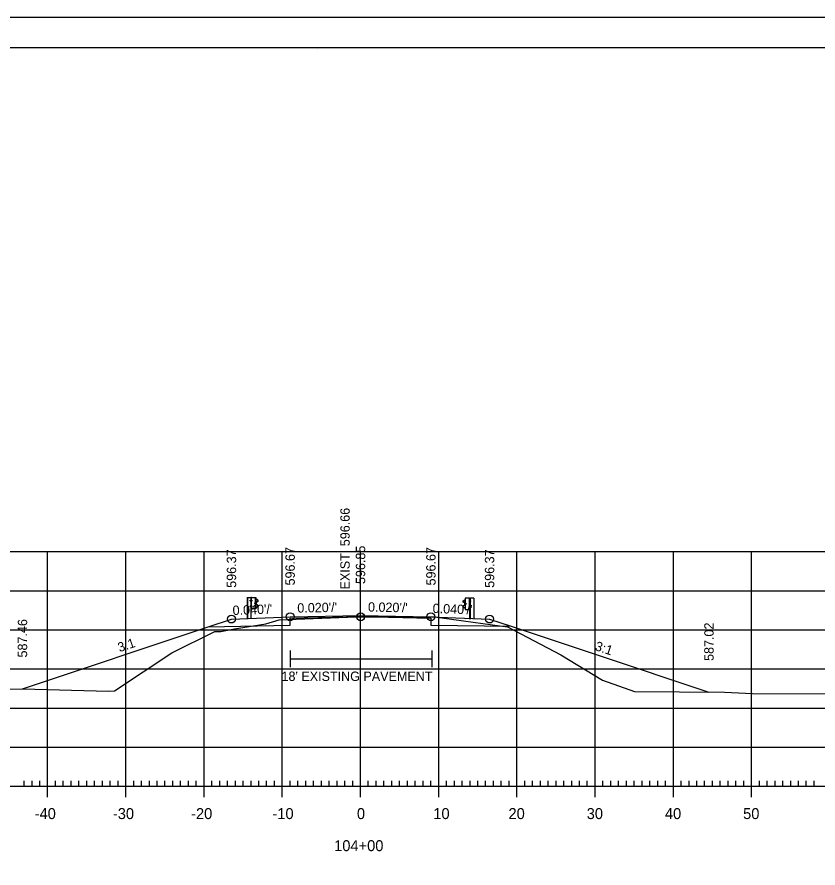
# Model space of a CAD drawing. Extents: x 961436 to 1372525, y 380079 to 2027791.
# Drawn here: x 1370589.9 to 1370692.3, y 380213.6 to 380322.4 of the extents above; entities that cross this region are included whole.
import ezdxf

# ---------------------------------------------------------------- set-up
doc = ezdxf.new("R2010")
doc.units = 0
for name, color, linetype in [('R_Alt Surface', 7, 'Continuous'), ('R_Axis', 7, 'Continuous'), ('R_Axis Annot', 7, 'Continuous'), ('R_Drive', 7, 'Continuous'), ('R_Exist Surface', 7, 'Continuous'), ('R_Fin Surface', 7, 'Continuous'), ('R_Fin Surface Annot', 7, 'Continuous'), ('R_Grid', 7, 'Continuous'), ('R_No Plot', 7, 'Continuous'), ('R_Proposed Road', 7, 'Continuous'), ('R_Xsect Elev', 7, 'Continuous')]:
    doc.layers.add(name, color=color, linetype=linetype)

msp = doc.modelspace()

# ---------------------------------------------------------------- linework, layer by layer
at = {"layer": 'R_Alt Surface'}
msp.add_lwpolyline([(1370614.33, 380244.44), (1370624.81, 380244.65), (1370624.8, 380244.65), (1370624.81, 380245.56), (1370633.81, 380245.74), (1370642.81, 380245.56), (1370642.82, 380244.65), (1370642.81, 380244.65), (1370653.07, 380244.51)], dxfattribs=at)
at = {"layer": 'R_Axis'}
for p, q in [((1370593.81, 380222.66), (1370593.81, 380225.46)), ((1370603.81, 380222.66), (1370603.81, 380225.46)), ((1370613.81, 380222.66), (1370613.81, 380225.46)), ((1370623.81, 380222.66), (1370623.81, 380225.46)), ((1370633.81, 380222.66), (1370633.81, 380225.46)), ((1370643.81, 380222.66), (1370643.81, 380225.46)), ((1370653.81, 380222.66), (1370653.81, 380225.46)), ((1370663.81, 380222.66), (1370663.81, 380225.46)), ((1370673.81, 380222.66), (1370673.81, 380225.46)), ((1370683.81, 380222.66), (1370683.81, 380225.46)), ((1370493.81, 380224.06), (1370773.81, 380224.06)), ((1370590.81, 380224.06), (1370590.81, 380224.76)), ((1370591.81, 380224.06), (1370591.81, 380224.76)), ((1370592.81, 380224.06), (1370592.81, 380224.76)), ((1370594.81, 380224.06), (1370594.81, 380224.76)), ((1370595.81, 380224.06), (1370595.81, 380224.76)), ((1370596.81, 380224.06), (1370596.81, 380224.76)), ((1370597.81, 380224.06), (1370597.81, 380224.76)), ((1370598.81, 380224.06), (1370598.81, 380224.76)), ((1370599.81, 380224.06), (1370599.81, 380224.76)), ((1370600.81, 380224.06), (1370600.81, 380224.76)), ((1370601.81, 380224.06), (1370601.81, 380224.76)), ((1370602.81, 380224.06), (1370602.81, 380224.76)), ((1370604.81, 380224.06), (1370604.81, 380224.76)), ((1370605.81, 380224.06), (1370605.81, 380224.76)), ((1370606.81, 380224.06), (1370606.81, 380224.76)), ((1370607.81, 380224.06), (1370607.81, 380224.76)), ((1370608.81, 380224.06), (1370608.81, 380224.76)), ((1370609.81, 380224.06), (1370609.81, 380224.76)), ((1370610.81, 380224.06), (1370610.81, 380224.76)), ((1370611.81, 380224.06), (1370611.81, 380224.76)), ((1370612.81, 380224.06), (1370612.81, 380224.76)), ((1370614.81, 380224.06), (1370614.81, 380224.76)), ((1370615.81, 380224.06), (1370615.81, 380224.76)), ((1370616.81, 380224.06), (1370616.81, 380224.76)), ((1370617.81, 380224.06), (1370617.81, 380224.76)), ((1370618.81, 380224.06), (1370618.81, 380224.76)), ((1370619.81, 380224.06), (1370619.81, 380224.76)), ((1370620.81, 380224.06), (1370620.81, 380224.76)), ((1370621.81, 380224.06), (1370621.81, 380224.76)), ((1370622.81, 380224.06), (1370622.81, 380224.76)), ((1370624.81, 380224.06), (1370624.81, 380224.76)), ((1370625.81, 380224.06), (1370625.81, 380224.76)), ((1370626.81, 380224.06), (1370626.81, 380224.76)), ((1370627.81, 380224.06), (1370627.81, 380224.76)), ((1370628.81, 380224.06), (1370628.81, 380224.76)), ((1370629.81, 380224.06), (1370629.81, 380224.76)), ((1370630.81, 380224.06), (1370630.81, 380224.76)), ((1370631.81, 380224.06), (1370631.81, 380224.76)), ((1370632.81, 380224.06), (1370632.81, 380224.76)), ((1370634.81, 380224.06), (1370634.81, 380224.76)), ((1370635.81, 380224.06), (1370635.81, 380224.76)), ((1370636.81, 380224.06), (1370636.81, 380224.76)), ((1370637.81, 380224.06), (1370637.81, 380224.76)), ((1370638.81, 380224.06), (1370638.81, 380224.76)), ((1370639.81, 380224.06), (1370639.81, 380224.76)), ((1370640.81, 380224.06), (1370640.81, 380224.76)), ((1370641.81, 380224.06), (1370641.81, 380224.76)), ((1370642.81, 380224.06), (1370642.81, 380224.76)), ((1370644.81, 380224.06), (1370644.81, 380224.76)), ((1370645.81, 380224.06), (1370645.81, 380224.76)), ((1370646.81, 380224.06), (1370646.81, 380224.76)), ((1370647.81, 380224.06), (1370647.81, 380224.76)), ((1370648.81, 380224.06), (1370648.81, 380224.76)), ((1370649.81, 380224.06), (1370649.81, 380224.76)), ((1370650.81, 380224.06), (1370650.81, 380224.76)), ((1370651.81, 380224.06), (1370651.81, 380224.76)), ((1370652.81, 380224.06), (1370652.81, 380224.76)), ((1370654.81, 380224.06), (1370654.81, 380224.76)), ((1370655.81, 380224.06), (1370655.81, 380224.76)), ((1370656.81, 380224.06), (1370656.81, 380224.76)), ((1370657.81, 380224.06), (1370657.81, 380224.76)), ((1370658.81, 380224.06), (1370658.81, 380224.76)), ((1370659.81, 380224.06), (1370659.81, 380224.76)), ((1370660.81, 380224.06), (1370660.81, 380224.76)), ((1370661.81, 380224.06), (1370661.81, 380224.76)), ((1370662.81, 380224.06), (1370662.81, 380224.76)), ((1370664.81, 380224.06), (1370664.81, 380224.76)), ((1370665.81, 380224.06), (1370665.81, 380224.76)), ((1370666.81, 380224.06), (1370666.81, 380224.76)), ((1370667.81, 380224.06), (1370667.81, 380224.76)), ((1370668.81, 380224.06), (1370668.81, 380224.76)), ((1370669.81, 380224.06), (1370669.81, 380224.76)), ((1370670.81, 380224.06), (1370670.81, 380224.76)), ((1370671.81, 380224.06), (1370671.81, 380224.76)), ((1370672.81, 380224.06), (1370672.81, 380224.76)), ((1370674.81, 380224.06), (1370674.81, 380224.76)), ((1370675.81, 380224.06), (1370675.81, 380224.76)), ((1370676.81, 380224.06), (1370676.81, 380224.76)), ((1370677.81, 380224.06), (1370677.81, 380224.76)), ((1370678.81, 380224.06), (1370678.81, 380224.76)), ((1370679.81, 380224.06), (1370679.81, 380224.76)), ((1370680.81, 380224.06), (1370680.81, 380224.76)), ((1370681.81, 380224.06), (1370681.81, 380224.76)), ((1370682.81, 380224.06), (1370682.81, 380224.76)), ((1370684.81, 380224.06), (1370684.81, 380224.76)), ((1370685.81, 380224.06), (1370685.81, 380224.76)), ((1370686.81, 380224.06), (1370686.81, 380224.76)), ((1370687.81, 380224.06), (1370687.81, 380224.76)), ((1370688.81, 380224.06), (1370688.81, 380224.76)), ((1370689.81, 380224.06), (1370689.81, 380224.76)), ((1370690.81, 380224.06), (1370690.81, 380224.76)), ((1370691.81, 380224.06), (1370691.81, 380224.76))]:
    msp.add_line(p, q, dxfattribs=at)
at = {"layer": 'R_Drive'}
for p, q in [((1370624.8, 380241.41), (1370624.8, 380239.27)), ((1370642.93, 380241.41), (1370642.93, 380239.27)), ((1370624.8, 380240.34), (1370642.93, 380240.34))]:
    msp.add_line(p, q, dxfattribs=at)
at = {"layer": 'R_Exist Surface'}
msp.add_lwpolyline([(1370585.4, 380236.48), (1370590.6, 380236.52), (1370601.58, 380236.21), (1370602.35, 380236.26), (1370609.7, 380241.1), (1370615.2, 380243.84), (1370615.97, 380243.85), (1370617.71, 380244.18), (1370621.7, 380244.81), (1370623.42, 380245.35), (1370632.16, 380245.68), (1370633.83, 380245.72), (1370635.84, 380245.71), (1370643.27, 380245.71), (1370650.69, 380244.68), (1370652.59, 380244.42), (1370659.43, 380240.87), (1370664.74, 380237.63), (1370668.86, 380236.15), (1370680.34, 380236.07), (1370683.94, 380235.93), (1370697.06, 380235.88)], dxfattribs=at)
at = {"layer": 'R_Fin Surface'}
msp.add_lwpolyline([(1370590.59, 380236.52), (1370614.33, 380244.44), (1370617.31, 380245.43), (1370624.81, 380245.73), (1370633.81, 380245.91), (1370642.81, 380245.73), (1370650.31, 380245.43), (1370653.07, 380244.51), (1370664.19, 380240.8), (1370678.36, 380236.08)], dxfattribs=at)
at = {"layer": 'R_Grid'}
for p, q in [((1370493.81, 380254.06), (1370773.81, 380254.06)), ((1370593.81, 380224.06), (1370593.81, 380254.06)), ((1370603.81, 380224.06), (1370603.81, 380254.06)), ((1370613.81, 380224.06), (1370613.81, 380254.06)), ((1370623.81, 380224.06), (1370623.81, 380254.06)), ((1370633.81, 380224.06), (1370633.81, 380254.06)), ((1370643.81, 380224.06), (1370643.81, 380254.06)), ((1370653.81, 380224.06), (1370653.81, 380254.06)), ((1370663.81, 380224.06), (1370663.81, 380254.06)), ((1370673.81, 380224.06), (1370673.81, 380254.06)), ((1370683.81, 380224.06), (1370683.81, 380254.06)), ((1370493.81, 380249.06), (1370773.81, 380249.06)), ((1370493.81, 380244.06), (1370773.81, 380244.06)), ((1370493.81, 380239.06), (1370773.81, 380239.06)), ((1370493.81, 380234.06), (1370773.81, 380234.06)), ((1370493.81, 380229.06), (1370773.81, 380229.06)), ((1370493.81, 380224.06), (1370773.81, 380224.06))]:
    msp.add_line(p, q, dxfattribs=at)
at = {"layer": 'R_No Plot'}
for p, q in [((1370463.41, 380322.41), (1370796.74, 380322.41)), ((1370475.81, 380318.52), (1370791.99, 380318.52)), ((1370628.33, 380318.26), (1370628.33, 380318.26)), ((1370628.33, 380318.26), (1370628.33, 380318.26))]:
    msp.add_line(p, q, dxfattribs=at)
for points in [[(1370463.4, 380322.41), (1370796.74, 380322.41), (1370796.74, 380109.08), (1370463.4, 380109.08)], [(1370709.73, 380318.52), (1370729.35, 380318.52), (1370729.35, 380308.64), (1370745.46, 380308.64), (1370768.66, 380308.64), (1370768.78, 380280.48), (1370791.99, 380280.48), (1370791.99, 380113.06), (1370475.81, 380113.06), (1370475.81, 380318.52)]]:
    msp.add_lwpolyline(points, close=True, dxfattribs=at)
for centre in [(1370617.31, 380245.43), (1370624.81, 380245.73), (1370633.83, 380245.72), (1370642.81, 380245.73), (1370650.31, 380245.43)]:
    msp.add_circle(centre, 0.5, dxfattribs=at)
at = {"layer": 'R_Proposed Road'}
for p, q in [((1370619.31, 380248.18), (1370619.31, 380245.51)), ((1370619.34, 380248.18), (1370619.34, 380245.51)), ((1370619.8, 380247.86), (1370619.74, 380247.86)), ((1370619.74, 380247.74), (1370619.74, 380247.84)), ((1370619.8, 380247.83), (1370619.74, 380247.83)), ((1370619.8, 380247.76), (1370619.74, 380247.76)), ((1370619.8, 380247.76), (1370619.75, 380247.76)), ((1370619.87, 380248.18), (1370619.8, 380248.18)), ((1370619.8, 380247.73), (1370619.8, 380247.86)), ((1370619.83, 380245.51), (1370619.83, 380248.18)), ((1370619.87, 380248.18), (1370619.86, 380248.18)), ((1370619.93, 380247.79), (1370619.87, 380247.79)), ((1370619.88, 380247.85), (1370619.93, 380247.85)), ((1370619.93, 380247.85), (1370619.93, 380247.72)), ((1370620.4, 380246.73), (1370620.4, 380248.17)), ((1370620.55, 380247.95), (1370620.43, 380248.02)), ((1370620.54, 380247.93), (1370620.44, 380247.99)), ((1370620.68, 380247.82), (1370620.54, 380247.93)), ((1370620.69, 380247.84), (1370620.55, 380247.95)), ((1370646.93, 380247.76), (1370647.07, 380247.87)), ((1370646.95, 380247.74), (1370647.09, 380247.85)), ((1370647.07, 380247.87), (1370647.19, 380247.94)), ((1370647.09, 380247.85), (1370647.18, 380247.91)), ((1370647.23, 380246.65), (1370647.23, 380248.09)), ((1370647.75, 380247.77), (1370647.7, 380247.77)), ((1370647.7, 380247.77), (1370647.7, 380247.64)), ((1370647.75, 380248.1), (1370647.76, 380248.1)), ((1370647.75, 380248.1), (1370647.83, 380248.1)), ((1370647.79, 380245.43), (1370647.79, 380248.1)), ((1370647.83, 380247.65), (1370647.83, 380247.78)), ((1370647.83, 380247.78), (1370647.88, 380247.78)), ((1370647.83, 380247.75), (1370647.88, 380247.75)), ((1370647.89, 380247.66), (1370647.89, 380247.76)), ((1370648.28, 380248.1), (1370648.28, 380245.43)), ((1370648.31, 380248.1), (1370648.31, 380245.43)), ((1370619.78, 380247.13), (1370619.73, 380247.13)), ((1370619.73, 380247.01), (1370619.73, 380247.11)), ((1370619.78, 380247.1), (1370619.73, 380247.1)), ((1370619.78, 380247.03), (1370619.73, 380247.03)), ((1370619.78, 380247), (1370619.73, 380247)), ((1370619.8, 380247.73), (1370619.74, 380247.73)), ((1370619.78, 380247.03), (1370619.74, 380247.03)), ((1370619.78, 380247), (1370619.78, 380247.13)), ((1370619.87, 380246.73), (1370619.83, 380246.73)), ((1370619.93, 380247.06), (1370619.87, 380247.06)), ((1370619.88, 380247.72), (1370619.93, 380247.72)), ((1370619.93, 380247.13), (1370619.88, 380247.13)), ((1370619.93, 380247), (1370619.88, 380247)), ((1370619.93, 380247), (1370619.93, 380247.13)), ((1370620.39, 380247.52), (1370620.33, 380247.52)), ((1370620.33, 380247.4), (1370620.33, 380247.5)), ((1370620.39, 380247.49), (1370620.33, 380247.49)), ((1370620.39, 380247.42), (1370620.33, 380247.42)), ((1370620.39, 380247.39), (1370620.33, 380247.39)), ((1370620.39, 380247.42), (1370620.34, 380247.42)), ((1370620.39, 380247.39), (1370620.39, 380247.52)), ((1370620.43, 380246.9), (1370620.54, 380246.96)), ((1370620.44, 380247.39), (1370620.44, 380247.53)), ((1370620.44, 380246.88), (1370620.56, 380246.94)), ((1370620.47, 380247.39), (1370620.47, 380247.53)), ((1370620.49, 380247.6), (1370620.67, 380247.71)), ((1370620.65, 380247.2), (1370620.49, 380247.31)), ((1370620.5, 380247.58), (1370620.69, 380247.69)), ((1370620.66, 380247.23), (1370620.5, 380247.33)), ((1370620.54, 380246.96), (1370620.68, 380247.07)), ((1370620.56, 380246.94), (1370620.69, 380247.06)), ((1370647.07, 380246.86), (1370646.93, 380246.98)), ((1370647.12, 380247.5), (1370646.94, 380247.61)), ((1370647.13, 380247.52), (1370646.95, 380247.63)), ((1370647.08, 380246.88), (1370646.95, 380246.99)), ((1370646.96, 380247.15), (1370647.13, 380247.25)), ((1370646.97, 380247.12), (1370647.14, 380247.23)), ((1370647.19, 380246.8), (1370647.07, 380246.86)), ((1370647.2, 380246.82), (1370647.08, 380246.88)), ((1370647.16, 380247.31), (1370647.16, 380247.45)), ((1370647.18, 380247.31), (1370647.18, 380247.45)), ((1370647.24, 380247.31), (1370647.24, 380247.44)), ((1370647.24, 380247.44), (1370647.29, 380247.44)), ((1370647.24, 380247.41), (1370647.29, 380247.41)), ((1370647.24, 380247.34), (1370647.28, 380247.34)), ((1370647.24, 380247.34), (1370647.29, 380247.34)), ((1370647.24, 380247.31), (1370647.29, 380247.31)), ((1370647.3, 380247.32), (1370647.3, 380247.42)), ((1370647.7, 380247.71), (1370647.76, 380247.71)), ((1370647.75, 380247.64), (1370647.7, 380247.64)), ((1370647.7, 380246.92), (1370647.7, 380247.05)), ((1370647.7, 380247.05), (1370647.75, 380247.05)), ((1370647.7, 380246.98), (1370647.76, 380246.98)), ((1370647.7, 380246.92), (1370647.75, 380246.92)), ((1370647.76, 380246.65), (1370647.79, 380246.65)), ((1370647.83, 380247.68), (1370647.87, 380247.68)), ((1370647.83, 380247.68), (1370647.88, 380247.68)), ((1370647.83, 380247.65), (1370647.88, 380247.65)), ((1370647.84, 380246.92), (1370647.84, 380247.05)), ((1370647.84, 380247.05), (1370647.89, 380247.05)), ((1370647.84, 380247.02), (1370647.89, 380247.02)), ((1370647.84, 380246.95), (1370647.89, 380246.95)), ((1370647.84, 380246.95), (1370647.89, 380246.95)), ((1370647.84, 380246.92), (1370647.89, 380246.92)), ((1370647.9, 380246.93), (1370647.9, 380247.03))]:
    msp.add_line(p, q, dxfattribs=at)
for points in [[(1370619.31, 380248.18), (1370619.8, 380248.18), (1370619.79, 380245.51)], [(1370648.31, 380248.1), (1370647.83, 380248.1), (1370647.83, 380245.43)]]:
    msp.add_lwpolyline(points, dxfattribs=at)
for points in [[(1370619.73, 380247.83), (1370619.73, 380247.76), (1370619.71, 380247.76), (1370619.71, 380247.83)], [(1370619.79, 380247.88), (1370619.79, 380247.7), (1370619.8, 380247.7), (1370619.8, 380247.88)], [(1370620.43, 380248.18), (1370620.43, 380246.73), (1370619.87, 380246.73), (1370619.87, 380248.18)], [(1370619.93, 380247.85), (1370619.93, 380247.72), (1370619.87, 380247.72), (1370619.87, 380247.85)], [(1370647.2, 380248.1), (1370647.2, 380246.65), (1370647.76, 380246.65), (1370647.75, 380248.1)], [(1370647.7, 380247.77), (1370647.7, 380247.64), (1370647.75, 380247.64), (1370647.75, 380247.77)], [(1370647.83, 380247.8), (1370647.83, 380247.62), (1370647.82, 380247.62), (1370647.82, 380247.8)], [(1370647.89, 380247.75), (1370647.89, 380247.68), (1370647.92, 380247.68), (1370647.92, 380247.75)], [(1370619.72, 380247.1), (1370619.72, 380247.03), (1370619.7, 380247.03), (1370619.7, 380247.1)], [(1370619.78, 380247.15), (1370619.78, 380246.97), (1370619.79, 380246.97), (1370619.79, 380247.15)], [(1370619.93, 380247.13), (1370619.93, 380247), (1370619.87, 380247), (1370619.87, 380247.13)], [(1370620.33, 380247.49), (1370620.33, 380247.42), (1370620.3, 380247.42), (1370620.3, 380247.49)], [(1370620.38, 380247.54), (1370620.38, 380247.36), (1370620.4, 380247.36), (1370620.4, 380247.54)], [(1370647.24, 380247.46), (1370647.24, 380247.28), (1370647.23, 380247.28), (1370647.23, 380247.46)], [(1370647.3, 380247.41), (1370647.3, 380247.34), (1370647.33, 380247.34), (1370647.33, 380247.41)], [(1370647.7, 380247.05), (1370647.7, 380246.92), (1370647.75, 380246.92), (1370647.75, 380247.05)], [(1370647.84, 380247.07), (1370647.84, 380246.89), (1370647.83, 380246.89), (1370647.83, 380247.07)], [(1370647.9, 380247.02), (1370647.9, 380246.95), (1370647.93, 380246.95), (1370647.93, 380247.02)]]:
    msp.add_lwpolyline(points, close=True, dxfattribs=at)
for centre, radius, start, end in [((1370619.76, 380247.84), 0.0234, 134.5745, 222.2244), ((1370619.84, 380247.79), 0.0979, 159.7423, 200.2577), ((1370619.76, 380247.74), 0.0265, 140.9334, 216.6234), ((1370620.64, 380247.77), 0.0658, 299.2499, 57.9783), ((1370620.64, 380247.77), 0.0909, 299.2499, 57.9783), ((1370646.98, 380247.69), 0.0909, 122.0217, 240.7501), ((1370646.98, 380247.69), 0.0658, 122.0217, 240.7501), ((1370647.86, 380247.76), 0.0234, 317.7756, 45.4255), ((1370647.79, 380247.71), 0.0979, 339.7423, 20.2577), ((1370619.75, 380247.11), 0.0234, 134.5745, 222.2244), ((1370619.82, 380247.06), 0.0979, 159.7423, 200.2577), ((1370619.75, 380247.01), 0.0265, 140.9334, 216.6234), ((1370620.35, 380247.5), 0.0234, 134.5745, 222.2244), ((1370620.43, 380247.45), 0.0979, 159.7423, 200.2577), ((1370620.35, 380247.4), 0.0265, 140.9334, 216.6234), ((1370620.53, 380247.52), 0.0918, 118.106, 175.0444), ((1370620.51, 380247.38), 0.0747, 171.7804, 246.8536), ((1370620.46, 380247.45), 0.0481, 282.9554, 86.0697), ((1370620.53, 380247.52), 0.066, 118.106, 175.0444), ((1370620.51, 380247.38), 0.049, 171.7804, 246.8536), ((1370620.6, 380247.13), 0.0907, 325.2184, 59.12), ((1370620.6, 380247.13), 0.116, 325.2184, 59.12), ((1370647.02, 380247.05), 0.116, 120.88, 214.7816), ((1370647.02, 380247.05), 0.0907, 120.88, 214.7816), ((1370647.09, 380247.44), 0.066, 4.9556, 61.894), ((1370647.16, 380247.37), 0.0481, 93.9303, 257.0446), ((1370647.09, 380247.44), 0.0918, 4.9556, 61.894), ((1370647.11, 380247.3), 0.049, 293.1464, 8.2196), ((1370647.11, 380247.3), 0.0747, 293.1464, 8.2196), ((1370647.27, 380247.42), 0.0234, 317.7756, 45.4255), ((1370647.2, 380247.37), 0.0979, 339.7423, 20.2577), ((1370647.27, 380247.32), 0.0265, 323.3766, 39.0666), ((1370647.86, 380247.66), 0.0265, 323.3766, 39.0666), ((1370647.88, 380247.03), 0.0234, 317.7756, 45.4255), ((1370647.8, 380246.98), 0.0979, 339.7423, 20.2577), ((1370647.87, 380246.93), 0.0265, 323.3766, 39.0666)]:
    msp.add_arc(centre, radius, start, end, dxfattribs=at)

# ---------------------------------------------------------------- texts
at = {"layer": 'R_Axis Annot'}
for s, p in [('-40', (1370592.15, 380219.86)), ('-30', (1370602.15, 380219.86)), ('-20', (1370612.15, 380219.86)), ('-10', (1370622.55, 380219.86)), ('0', (1370633.35, 380219.86)), ('10', (1370643.12, 380219.86)), ('20', (1370652.73, 380219.86)), ('30', (1370662.73, 380219.86)), ('40', (1370672.73, 380219.86)), ('50', (1370682.73, 380219.86)), ('104+00', (1370630.44, 380215.76))]:
    msp.add_text(s, height=1.4, dxfattribs=at).set_placement(p)
at = {"layer": 'R_Fin Surface Annot'}
for s, rotation, p in [('596.67', 90, (1370625.41, 380249.73)), ('596.85', 90, (1370634.41, 380249.91)), ('596.67', 90, (1370643.41, 380249.73)), ('596.37', 90, (1370617.91, 380249.43)), ('596.37', 90, (1370650.91, 380249.43)), ("0.040'/'", 2.2906, (1370617.48, 380245.94)), ("0.020'/'", 1.1458, (1370625.74, 380246.25)), ("0.020'/'", 358.8542, (1370634.76, 380246.39)), ("0.040'/'", 357.7094, (1370643.02, 380246.22)), ('587.46', 90, (1370591.19, 380240.52)), ('587.02', 90, (1370678.96, 380240.08)), ('3:1', 18.4349, (1370603, 380241.19)), ('3:1', 341.5651, (1370663.7, 380241.49))]:
    msp.add_text(s, height=1.2, rotation=rotation, dxfattribs=at).set_placement(p)
msp.add_text("18' EXISTING PAVEMENT", height=1.2, dxfattribs=at).set_placement((1370623.71, 380237.52))
at = {"layer": 'R_Xsect Elev'}
msp.add_text('EXIST. 596.66', height=1.2, rotation=90, dxfattribs=at).set_placement((1370632.43, 380249.22))

doc.saveas('drawing.dxf')
